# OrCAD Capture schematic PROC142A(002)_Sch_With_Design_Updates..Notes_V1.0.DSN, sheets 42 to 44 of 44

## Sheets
42 42. OSCILLATOR: size C; title: OSCILLATOR
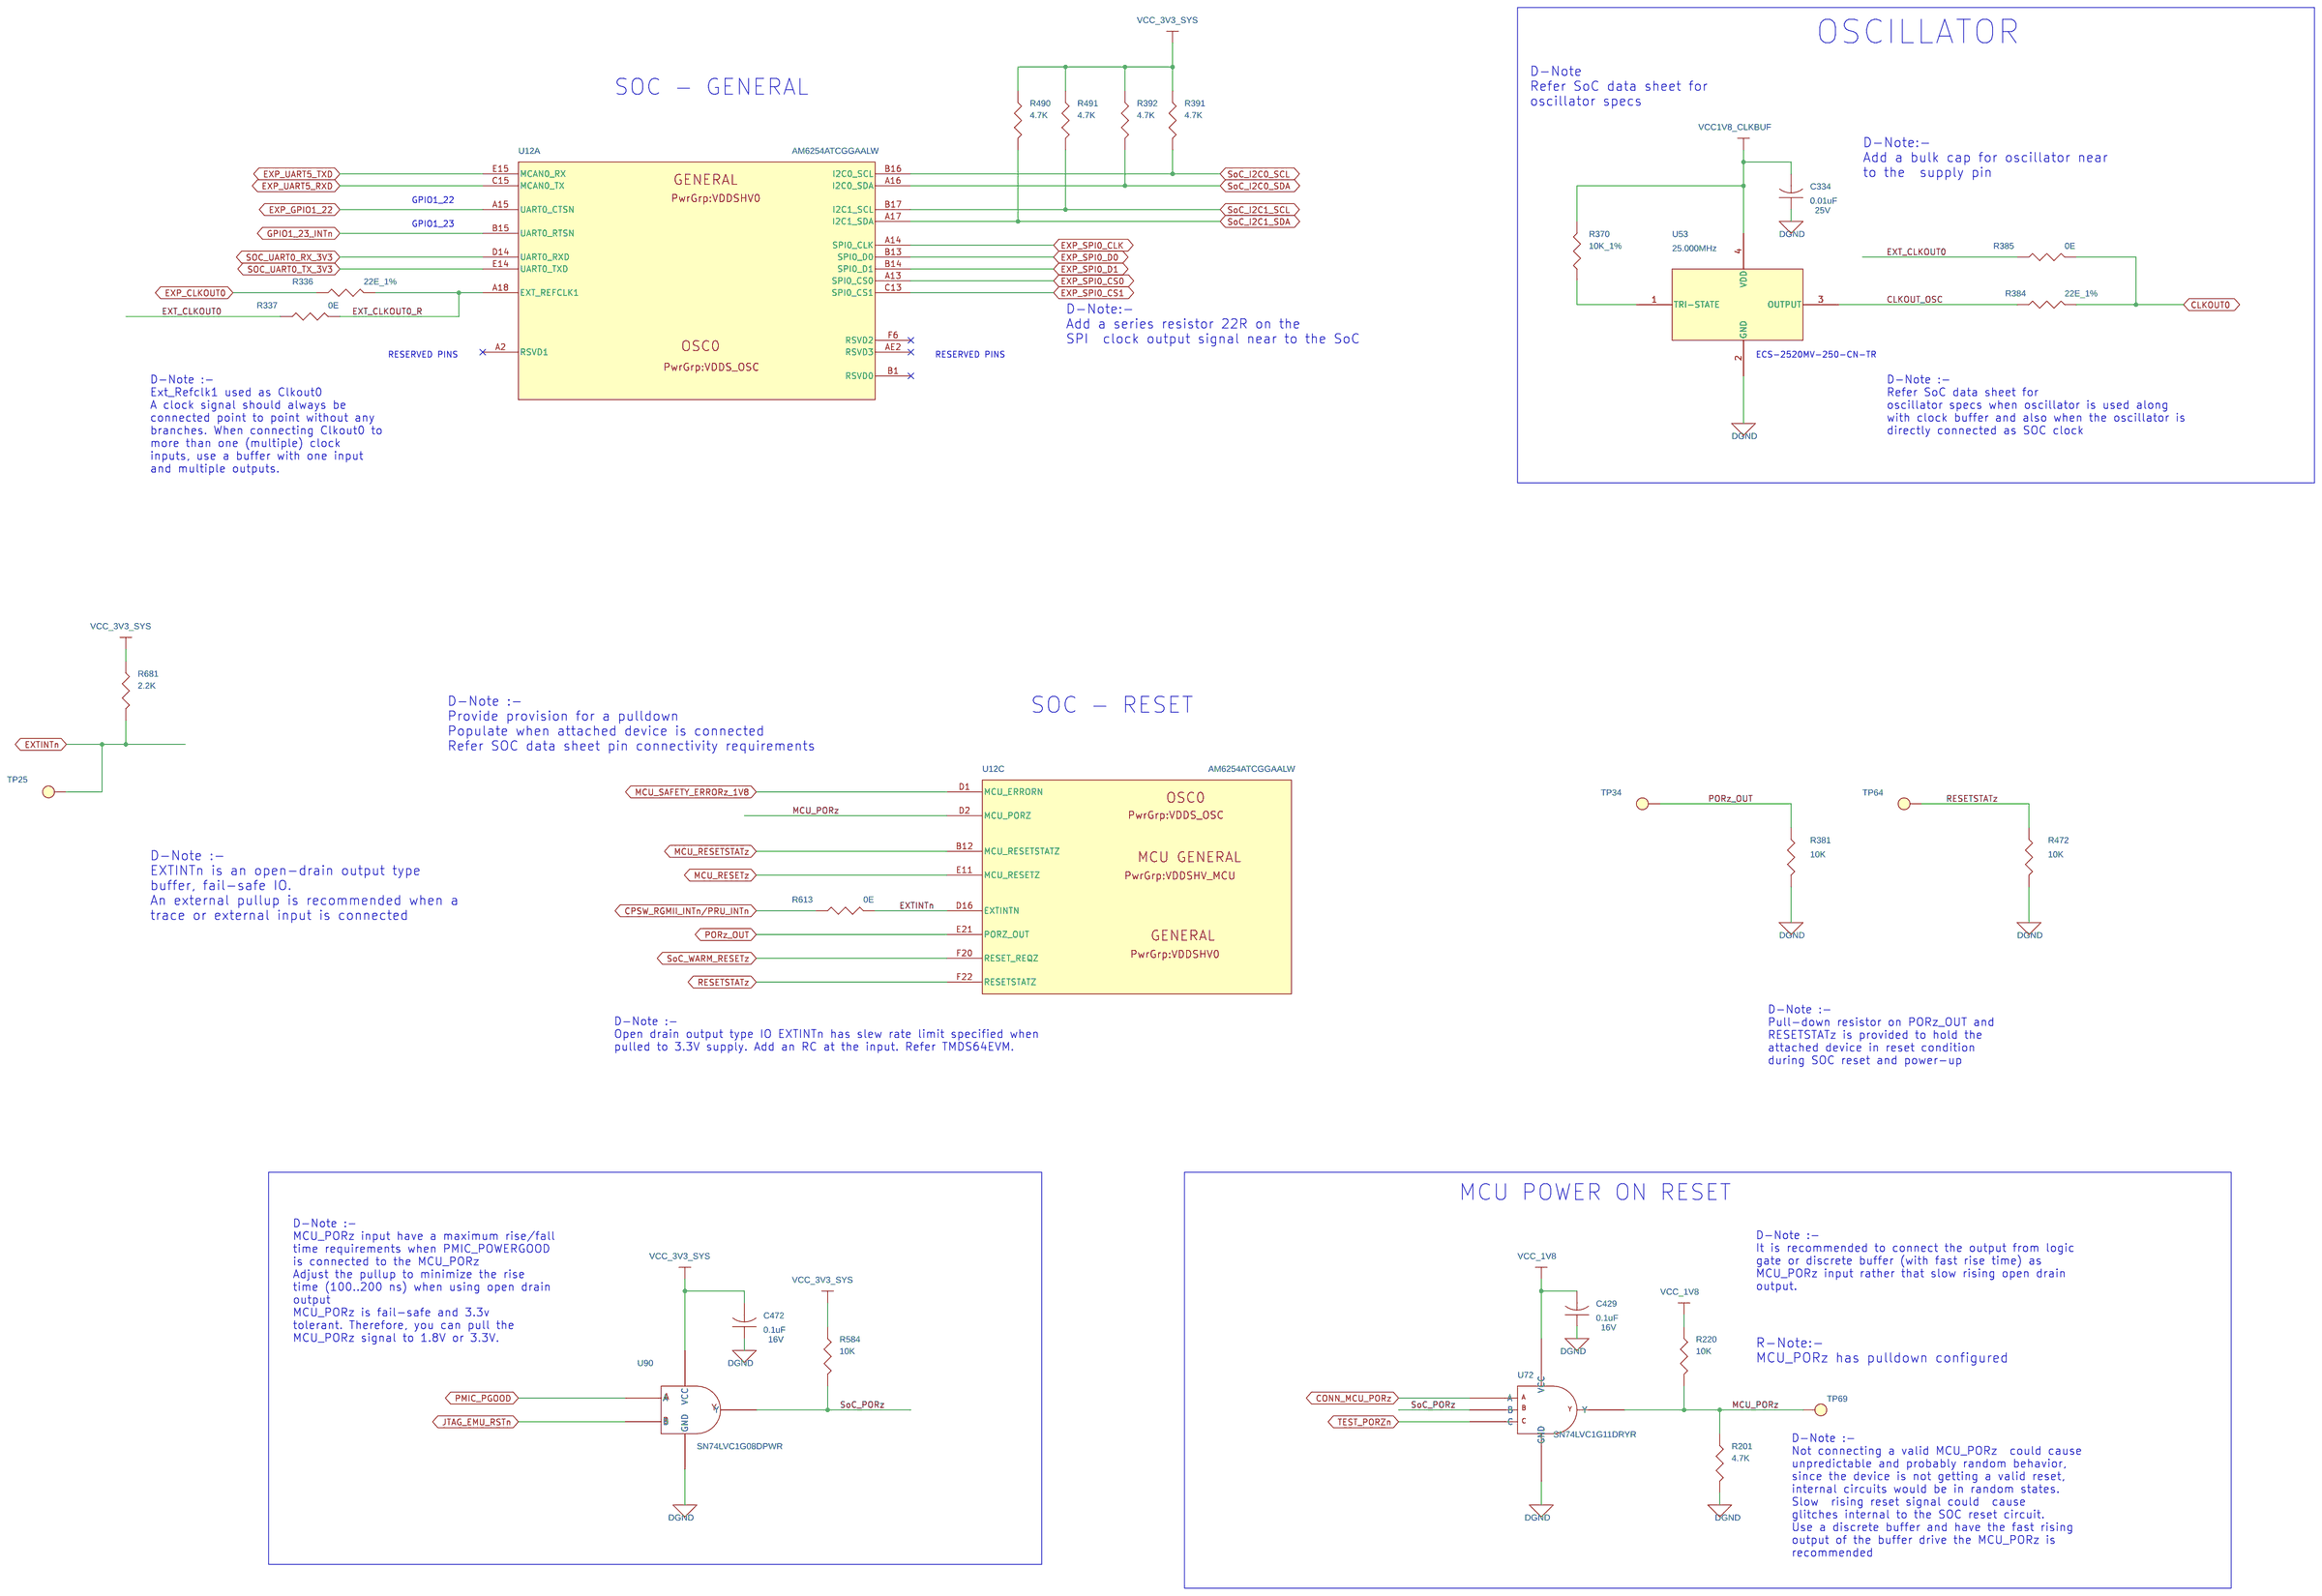
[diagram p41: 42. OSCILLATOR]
43 43. RESET: size C; title: RESET
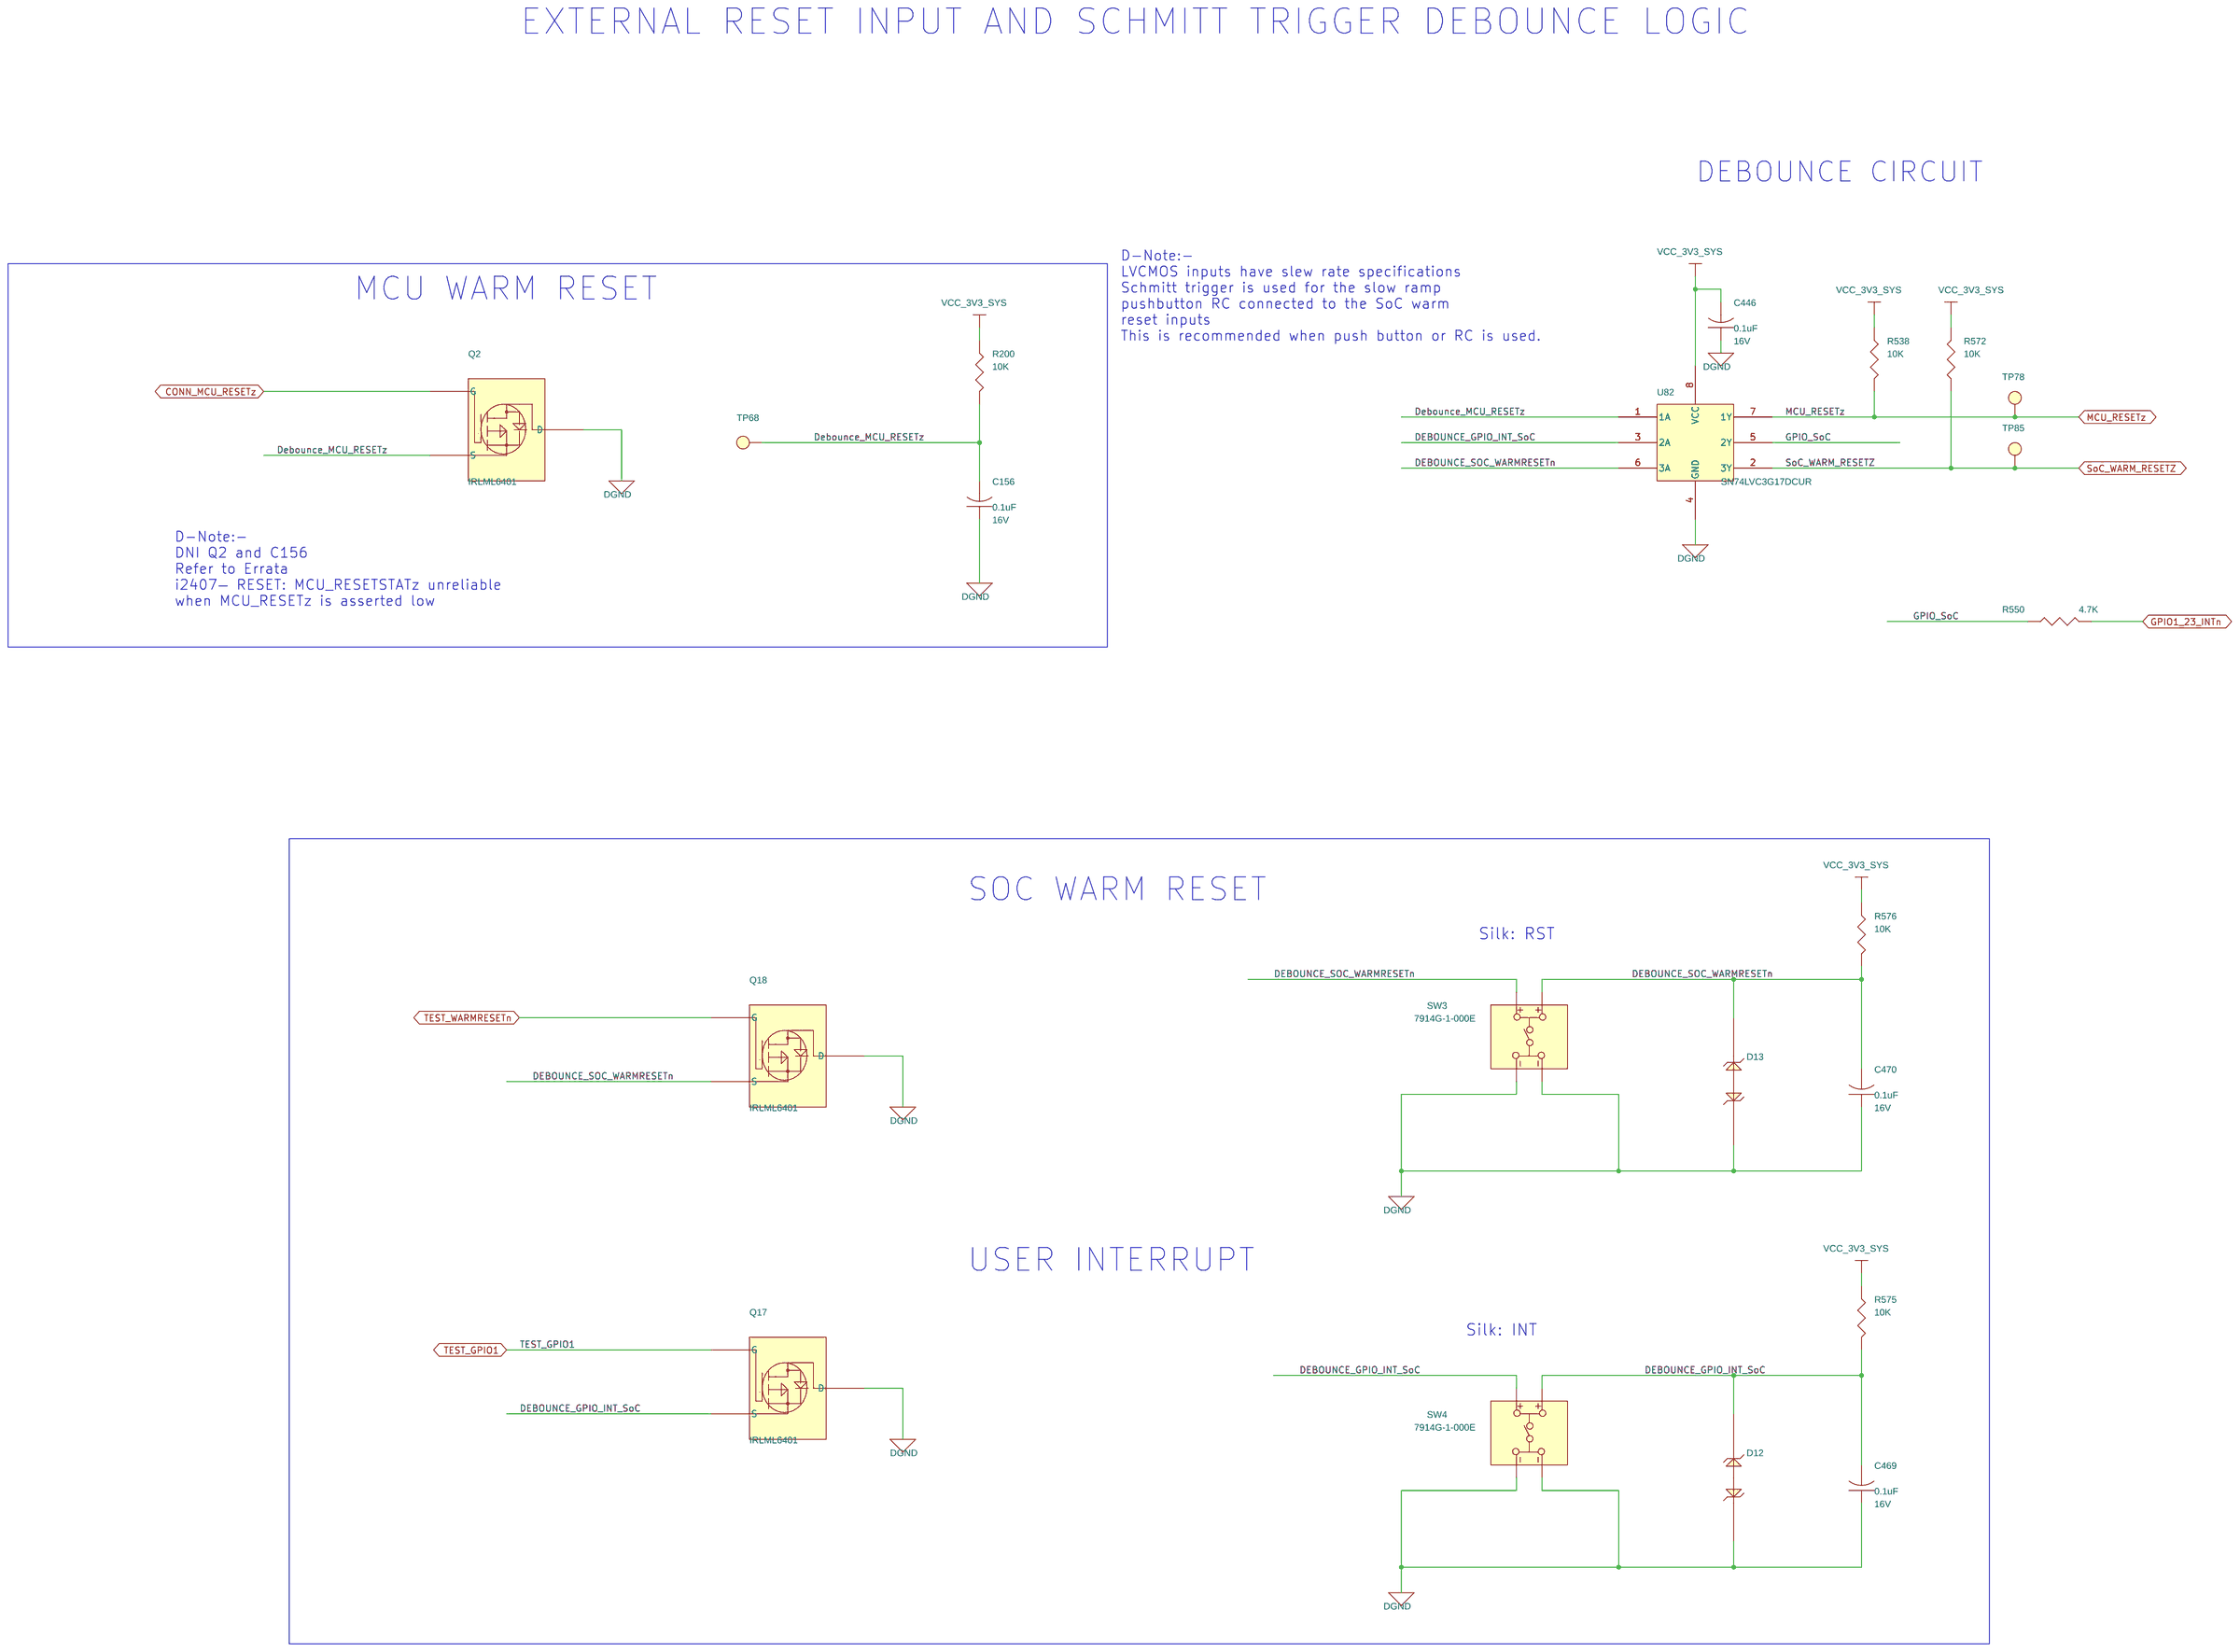
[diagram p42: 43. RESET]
44 44. ACCESSORIES: title: HARDWARE SCHEMATICS
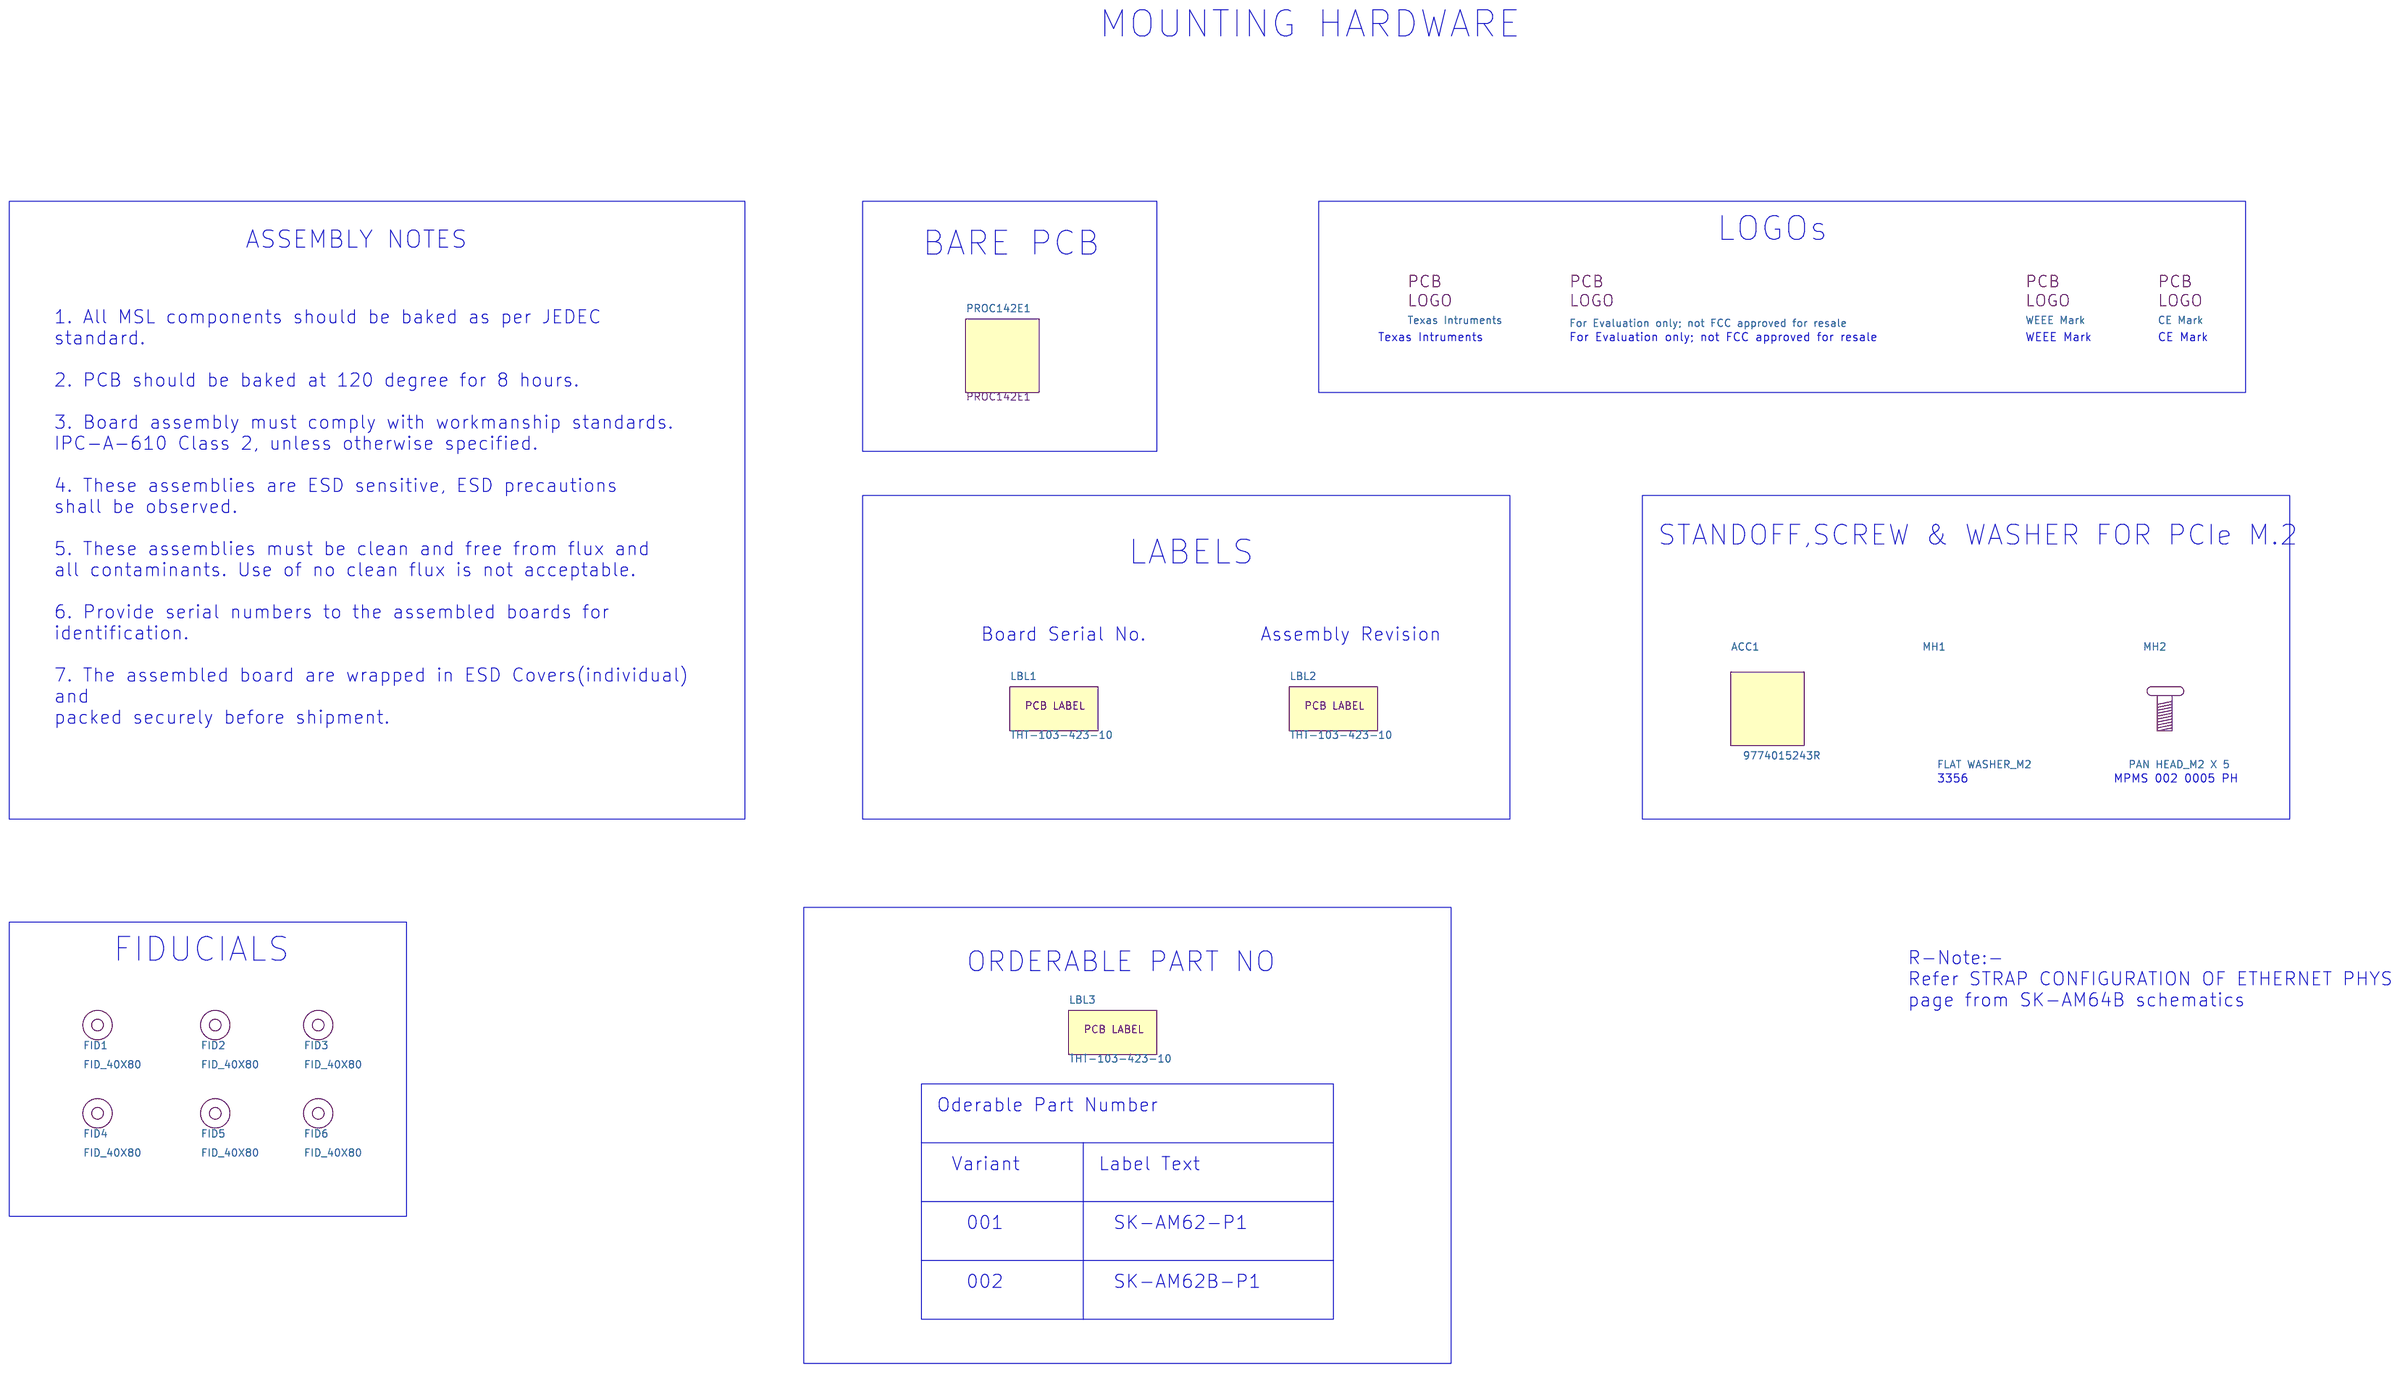
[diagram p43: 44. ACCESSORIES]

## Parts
sheet 42. OSCILLATOR
C334  0.01uF  [CAP0201_0-5]
C429  0.1uF  [CAP0201_0-5]
C472  0.1uF  [CAP0201_0-5]
R201  4.7K  [RES0201_0-5]
R220  10K  [RES0201_0-5]
R336  22E_1%  [RES0201_0-5]
R337  0E  [RES0201_0-5]
R370  10K_1%  [RES0201_0-5]
R381  10K  [RES0201_0-5]
R384  22E_1%  [RES0201_0-5]
R385  0E  [RES0201_0-5]
R391  4.7K  [RES0201_0-5]
R392  4.7K  [RES0201_0-5]
R472  10K  [RES0201_0-5]
R490  4.7K  [RES0201_0-5]
R491  4.7K  [RES0201_0-5]
R584  10K  [RES0201_0-5]
R613  0E  [RES0201_0-5]
R681  2.2K  [RES0201_0-5]
TP25  TP20_SMD  [TP20_SMD]
TP34  TP20_SMD  [TP20_SMD]
TP64  TP20_SMD  [TP20_SMD]
TP69  TP20_SMD  [TP20_SMD]
U12  AM6254ATCGGAALW  [BGA425_19-68_510X510_0-7]  (sections A,B,C,D,E,F,G,H,I,J,K,L,M,N,O,P,Q,R)
U53  25.000MHz  [OSC4_ECS-2520MV_100X80_SMD_0-9]
U72  SN74LVC1G11DRYR  [SON6_SN74LVC2G17_40X60_0-6]
U90  SN74LVC1G08DPWR  [X2SON5_TLV7021_30X30_0-4]
sheet 43. RESET
C156  0.1uF  [CAP0201_0-5]
C446  0.1uF  [CAP0201_0-5]
C469  0.1uF  [CAP0201_0-5]
C470  0.1uF  [CAP0201_0-5]
D12  TPD1E10B06DPYR  [DIO_DFN0402_0-5]
D13  TPD1E10B06DPYR  [DIO_DFN0402_0-5]
Q2  IRLML6401  [TO_SOT23-123]
Q17  IRLML6401  [TO_SOT23-123]
Q18  IRLML6401  [TO_SOT23-123]
R200  10K  [RES0201_0-5]
R538  10K  [RES0201_0-5]
R550  4.7K  [RES0201_0-5]
R572  10K  [RES0201_0-5]
R575  10K  [RES0201_0-5]
R576  10K  [RES0201_0-5]
SW3  7914G-1-000E  [SW4_100X216_200X200_SMD_4-2]
SW4  7914G-1-000E  [SW4_100X216_200X200_SMD_4-2]
TP68  TP20_SMD  [TP20_SMD]
TP78  TP20_SMD  [TP20_SMD]
TP85  TP20_SMD  [TP20_SMD]
U82  SN74LVC3G17DCUR  [VSSOP8_19-68_85X95_0-9]
sheet 44. ACCESSORIES
ACC1  9774015243R  [NA]
FID1  FID_40X80  [FID_40X80]
FID2  FID_40X80  [FID_40X80]
FID3  FID_40X80  [FID_40X80]
FID4  FID_40X80  [FID_40X80]
FID5  FID_40X80  [FID_40X80]
FID6  FID_40X80  [FID_40X80]
LBL1  THT-103-423-10  [NA]
LBL2  THT-103-423-10  [NA]
LBL3  THT-103-423-10  [NA]
LOGO1  Texas Intruments  [TI_Stacked_Overlay_Small]
LOGO2  For Evaluation only; not FCC approved for resale  [FCC_disclaimer]
LOGO3  WEEE Mark  [TI_Stacked_Overlay_Small]
LOGO4  CE Mark  [TI_Stacked_Overlay_Small]
MH1  FLAT WASHER_M2  [NA]
MH2  PAN HEAD_M2 X 5  [NA]
PCB1  PROC142E1

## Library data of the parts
C334 = CAP: CAP CERAMIC 0.01uF 25V 10% X5R 0201; Chkd/date: MANIRAJA/230118; Crtd /date: MANIRAJA/230118; Custom_Duty: 15%; Customs_HS_Code: 85322990; Distributor_name: DIGIKEY; Distributor_part_number: GRM033R61E103KA12J-ND; Footprint Path: Y:\MIS_DATABASE\Library\ALTIUM_TOOL\PCB_FOOTPRINTS\Altium_Footprint_Lib.PcbLib; Height: 0.33MM; Library Path: Y:\MIS_DATABASE\Library\ALTIUM_TOOL\SCHEMATICS_PARTS\MS_DISCRETE_Library.schlib; Mfr_name: MURATA; Mfr_part_number: GRM033R61E103KA12J; Mistral Part No: 120018010007-R; Package: 0201; Part_type: CAPACITORS\CERAMIC; Project: TI_MAXIE_CPB; RoHS: RoHS; Temperature: -55°C+85°C; Tolerance: 10%; Voltage: 25V; Wattage: NA; Weight: 0.33mg; Datasheet: Y:\MIS_DATABASE\DATASHEETS\CAPACITORS\GRM033R61E103KA12.PDF
C156 C429 C446 C469 C470 C472 = CAP: CAP CERAMIC 0.1uF 16V 10% X5R 0201; Alt_Mfr_name: YAGEO AMERICA; Alt_Mfr_part_number: CC0402KRX5R8BB104; Chkd/date: MANIRAJA/230118; Crtd /date: MANIRAJA/230118; Custom_Duty: 15%; Customs_HS_Code: 85322990; Distributor_name: DIGIKEY; Distributor_part_number: 490-14305-1-ND; Footprint Path: Y:\MIS_DATABASE\Library\ALTIUM_TOOL\PCB_FOOTPRINTS\Altium_Footprint_Lib.PcbLib; Height: 0.33MM; Library Path: Y:\MIS_DATABASE\Library\ALTIUM_TOOL\SCHEMATICS_PARTS\MS_DISCRETE_Library.schlib; Mfr_name: MURATA; Mfr_part_number: GRM033R61C104KE14D; Mistral Part No: 120009030072-R; Package: 0201; Part_type: CAPACITORS\CERAMIC; Project: TI_MAXIE_CPB; RoHS: RoHS; Temperature: -55°C+85°C; Tolerance: 10%; Voltage: 16V; Wattage: NA; Weight: 0.33mg; Datasheet: Y:\MIS_DATABASE\DATASHEETS\CAPACITORS\GRM033R61C104KE14.PDF
R201 R391 R392 R490 R491 = RESISTOR: RES 4.7K 1/20W 5% 0201; Chkd/date: MANIRAJA/200921; Crtd /date: ALVY/200921; Custom_Duty: 15%; Customs_HS_Code: 85332119; Distributor_name: DIGIKEY; Distributor_part_number: 311-4.7KNCT-ND; Footprint Path: Y:\MIS_DATABASE\Library\ALTIUM_TOOL\PCB_FOOTPRINTS\Altium_Footprint_Lib.PcbLib; Height: 0.26MM; Library Path: Y:\MIS_DATABASE\Library\ALTIUM_TOOL\SCHEMATICS_PARTS\MS_DISCRETE_Library.schlib; Mfr_name: YAGEO AMERICA; Mfr_part_number: RC0201JR-074K7L; Mistral Part No: 110021090007-R; Package: 0201; Part_type: RESISTORS\FIXED; Project: TI_AM62x SKEVM_BRD; RoHS: RoHS; Temperature: -55°C+125°C; Tolerance: 5%; Voltage: NA; Wattage: 1/20W; Weight: 0.17mg; Datasheet: Y:\MIS_DATABASE\DATASHEETS\RESISTORS\RCXXXXL-SER_MAR18.PDF
R200 R220 R381 R472 R538 R572 R575 R576 R584 = RESISTOR: RES 10K 1/20W 5% 0201; Chkd/date: MANIRAJA/050517; Crtd /date: MANIRAJA/050517; Custom_Duty: 15%; Customs_HS_Code: 85332119; Distributor_name: DIGIKEY; Distributor_part_number: 311-10KNCT-ND; Footprint Path: Y:\MIS_DATABASE\Library\ALTIUM_TOOL\PCB_FOOTPRINTS\Altium_Footprint_Lib.PcbLib; Height: 0.26MM; Library Path: Y:\MIS_DATABASE\Library\ALTIUM_TOOL\SCHEMATICS_PARTS\MS_DISCRETE_Library.schlib; Mfr_name: YAGEO AMERICA; Mfr_part_number: RC0201JR-0710KL; Mistral Part No: 110010070051-R; Package: 0201; Part_type: RESISTORS\FIXED; Project: GOLDEN-I LITE; RoHS: RoHS; Temperature: -55°C+125°C; Tolerance: 5%; Voltage: NA; Wattage: 1/20W; Weight: 0.17mg; Datasheet: Y:\MIS_DATABASE\DATASHEETS\RESISTORS\RCXXXXL-SER_MAR18.PDF
R336 R384 = RESISTOR: RES 22E 1/20W 1% 0201; Chkd/date: MAZHAR/140709; Crtd /date: MAZHAR/220807; Custom_Duty: 15%; Customs_HS_Code: 85332119; Distributor_name: DIGIKEY; Distributor_part_number: P22.0ABCT-ND; Footprint Path: Y:\MIS_DATABASE\Library\ALTIUM_TOOL\PCB_FOOTPRINTS\Altium_Footprint_Lib.PcbLib; Height: 0.26MM; Library Path: Y:\MIS_DATABASE\Library\ALTIUM_TOOL\SCHEMATICS_PARTS\MS_DISCRETE_Library.schlib; Mfr_name: PANASONIC-ECG; Mfr_part_number: ERJ-1GEF22R0C; Mistral Part No: 110009030522-R; Package: 0201; Part_type: RESISTORS\FIXED; Project: V8TS; RoHS: RoHS; Temperature: -55°C+125°C; Tolerance: 1%; Voltage: NA; Wattage: 1/20W; Weight: 0.15mg; Datasheet: Y:\MIS_DATABASE\DATASHEETS\RESISTORS\PAN-ERJSER_NOV17.PDF
R337 R385 R613 = RESISTOR: RES 0E 1/20W 5% 0201; Chkd/date: NAVEED/301214; Crtd /date: MUDDU/120710; Custom_Duty: 15%; Customs_HS_Code: 85332119; Distributor_name: DIGIKEY; Distributor_part_number: 311-0.0NCT-ND; Footprint Path: Y:\MIS_DATABASE\Library\ALTIUM_TOOL\PCB_FOOTPRINTS\Altium_Footprint_Lib.PcbLib; Height: 0.26MM; Library Path: Y:\MIS_DATABASE\Library\ALTIUM_TOOL\SCHEMATICS_PARTS\MS_DISCRETE_Library.schlib; Mfr_name: YAGEO AMERICA; Mfr_part_number: RC0201JR-070RL; Mistral Part No: 110010070067-R; Package: 0201; Part_type: RESISTORS\FIXED; Project: PB_BUGBASE; RoHS: RoHS; Temperature: -55°C+125°C; Tolerance: 5%; Voltage: NA; Wattage: 1/20W; Weight: 0.17mg; Datasheet: Y:\MIS_DATABASE\DATASHEETS\RESISTORS\RCXXXXL-SER_MAR18.PDF
R370 = RESISTOR: RES 10K 1/20W 1% 0201; Chkd/date: VASANTHA/270117; Crtd /date: MANIRAJA/270117; Custom_Duty: 15%; Customs_HS_Code: 85332119; Distributor_name: DIGIKEY; Distributor_part_number: 311-10.0KMCT-ND; Footprint Path: Y:\MIS_DATABASE\Library\ALTIUM_TOOL\PCB_FOOTPRINTS\Altium_Footprint_Lib.PcbLib; Height: 0.26MM; Library Path: Y:\MIS_DATABASE\Library\ALTIUM_TOOL\SCHEMATICS_PARTS\MS_DISCRETE_Library.schlib; Mfr_name: YAGEO AMERICA; Mfr_part_number: RC0201FR-0710KL; Mistral Part No: 110011040018-R; Package: 0201; Part_type: RESISTORS\FIXED; Project: GOLDEN-I LITE; RoHS: RoHS; Temperature: -55°C+125°C; Tolerance: 1%; Voltage: NA; Wattage: 1/20W; Weight: 0.17mg; Datasheet: Y:\MIS_DATABASE\DATASHEETS\RESISTORS\RCXXXXL-SER_MAR18.PDF
R681 = RESISTOR: RES 2.2K 1/20W 5% 0201; Chkd/date: VASANTHA/010117; Crtd /date: MAZHAR/010605; Custom_Duty: 15%; Customs_HS_Code: 85332119; Distributor_name: DIGIKEY; Distributor_part_number: P2.2KAGCT-ND; Footprint Path: Y:\MIS_DATABASE\Library\ALTIUM_TOOL\PCB_FOOTPRINTS\Altium_Footprint_Lib.PcbLib; Height: 0.26MM; Library Path: Y:\MIS_DATABASE\Library\ALTIUM_TOOL\SCHEMATICS_PARTS\MS_DISCRETE_Library.schlib; Mfr_name: PANASONIC-ECG; Mfr_part_number: ERJ-1GEJ222C; Mistral Part No: 110009030427-R; Package: 0201; Part_type: RESISTORS\FIXED; Project: G4SLIM; RoHS: RoHS; Temperature: -55°C+125°C; Tolerance: 5%; Voltage: NA; Wattage: 1/20W; Weight: 0.15mg; Datasheet: Y:\MIS_DATABASE\DATASHEETS\RESISTORS\PAN-ERJXGE-FEB06.PDF
TP25 TP34 TP64 TP68 TP69 TP78 TP85 = TESTPOINT: TESTPOINT CIR 20 SMD; Chkd/date: SHREESHAIL/171006; Crtd /date: MAZHAR/171006; Custom_Duty: NA; Customs_HS_Code: NA; Distributor_name: NA; Distributor_part_number: NA; Footprint Path: Y:\MIS_DATABASE\Library\ALTIUM_TOOL\PCB_FOOTPRINTS\Altium_Footprint_Lib.PcbLib; Height: NA; Library Path: Y:\MIS_DATABASE\Library\ALTIUM_TOOL\SCHEMATICS_PARTS\MS_DISCRETE_Library.schlib; MECHANICAL 3D STEP FILE: NA; Mfr_name: LOCAL; Mistral Part No: NA; Package: SMD; Project: BT MODULE_CSRBC04; RoHS: NA; Temperature: NA; Tolerance: NA; Voltage: NA; Wattage: NA; Weight: NA; Datasheet: NA
U12 = AM62-EVM_BGA425: IC AM62 SoC MICROPROCESSOR BGA425; Chkd/date: ALVY/110621; Crtd /date: MANIRAJA/110621; Custom_Duty: 15%; Customs_HS_Code: 85423100; Distributor_name: NA; Distributor_part_number: NA; Footprint Path: Y:\MIS_DATABASE\Library\ALTIUM_TOOL\PCB_FOOTPRINTS\Altium_Footprint_Lib.PcbLib; Height: 0.65MM; Library Path: Y:\MIS_DATABASE\Library\ALTIUM_TOOL\SCHEMATICS_PARTS\MS_MICROPROCESSOR_Library.schlib; Mfr_name: TEXAS INSTRUMENTS; Mistral Part No: 141221060001; Package: BGA425; Part_type: ICS\DIGITAL\MICROPROCESSOR; Project: AM62_EVM_BRD; RoHS: NA; Temperature: NA; Tolerance: NA; Voltage: NA; Wattage: NA; Weight: NA; Datasheet: Y:\MIS_DATABASE\DATASHEETS\ICS\DIGITAL\MICROCONTROLLER\AM62-SoC_SVB.PDF
U53 = OSC4_ASFL3: OSC 25.000MHz CMOS SMD; Chkd/date: MANIRAJA/181120; Crtd /date: ALVY/181120; Custom_Duty: 24%; Customs_HS_Code: 85437099; Distributor_name: DIGIKEY; Distributor_part_number: XC2752CT-ND; Footprint Path: Y:\MIS_DATABASE\Library\ALTIUM_TOOL\PCB_FOOTPRINTS\Altium_Footprint_Lib.PcbLib; Height: 0.90MM; Library Path: Y:\MIS_DATABASE\Library\ALTIUM_TOOL\SCHEMATICS_PARTS\MS_DISCRETE_Library.schlib; Mfr_name: ECS INC; Mfr_part_number: ECS-2520MV-250-CN-TR; Mistral Part No: 130020110041-R; Package: SMD; Part_type: OSCILLATORS; Project: AM64X_SKEVM; RoHS: RoHS; Temperature: -40°C+85°C; Tolerance: NA; Voltage: NA; Wattage: NA; Weight: 311mg; Datasheet: Y:\MIS_DATABASE\DATASHEETS\MISC\CRY_OSC\ECS-2520MV.PDF
U72 = SN74LVC1G11DCKR_SC70-6: IC SINGLE 3-INPUT POSITIVE-AND GATE SON6; Chkd/date: MANIRAJA/270121; Crtd /date: ALVY/270121; Custom_Duty: 15%; Customs_HS_Code: 85423100; Distributor_name: DIGIKEY; Distributor_part_number: 296-30120-1-ND; Footprint Path: Y:\MIS_DATABASE\Library\ALTIUM_TOOL\PCB_FOOTPRINTS\Altium_Footprint_Lib.PcbLib; Height: 0.60MM; Library Path: Y:\MIS_DATABASE\Library\ALTIUM_TOOL\SCHEMATICS_PARTS\MS_GATE_Library.schlib; Mfr_name: TEXAS INSTRUMENTS; Mistral Part No: 141021010013-R; Package: SON6; Part_type: ICS\DIGITAL\GATES; Project: AM64X_SKEVM; RoHS: RoHS; Temperature: -40°C+125°C; Tolerance: NA; Voltage: NA; Wattage: NA; Weight: 33mg; Datasheet: Y:\MIS_DATABASE\DATASHEETS\ICS\DIGITAL\GATES\SN74LVC1G_NOV16.PDF
U90 = 74AHC1G08GW_SOT353-5: IC SINGLE 2-INPUT POSITIVE-AND GATE X2SON5; Chkd/date: MANIRAJA/141020; Crtd /date: ALVY/131020; Custom_Duty: 15%; Customs_HS_Code: 85423100; Distributor_name: DIGIKEY; Distributor_part_number: 296-40549-1-ND; Footprint Path: Y:\MIS_DATABASE\Library\ALTIUM_TOOL\PCB_FOOTPRINTS\Altium_Footprint_Lib.PcbLib; Height: 0.40MM; Library Path: Y:\MIS_DATABASE\Library\ALTIUM_TOOL\SCHEMATICS_PARTS\MS_GATE_Library.schlib; Manufacturer: TEXAS INSTRUMENTS; Mistral Part No: 141020100009-R; Package: X2SON5; Part_type: ICS\DIGITAL\GATES; Project: AM64X_SKEVM; RoHS: RoHS; Temperature: -40°C+125°C; Tolerance: NA; Voltage: NA; Wattage: NA; Weight: 0.6mg; Datasheet: Y:\MIS_DATABASE\DATASHEETS\ICS\DIGITAL\GATES\SN74LVC1G08XX.PDF
D12 D13 = DIODE_SOD323: DIODE 1CH ESD PROTECTION X1SON2; Chkd/date: MANIRAJA/040420; Crtd /date: VASANTHA/181114; Custom_Duty: 15%; Customs_HS_Code: 85423100; Distributor_name: DIGIKEY; Distributor_part_number: 296-30406-1-ND; Footprint Path: Y:\MIS_DATABASE\Library\ALTIUM_TOOL\PCB_FOOTPRINTS\Altium_Footprint_Lib.PcbLib; Height: 0.45MM; Library Path: Y:\MIS_DATABASE\Library\ALTIUM_TOOL\SCHEMATICS_PARTS\MS_DISCRETE_Library.schlib; Mfr_name: TEXAS INSTRUMENTS; Mistral Part No: 130014110022-R; Package: X1SON2; Part_type: DIODE; Project: GALILEO_EVM; RoHS: RoHS; Temperature: -40°C+125°C; Tolerance: NA; Voltage: NA; Wattage: NA; Weight: 1mg; Datasheet: Y:\MIS_DATABASE\DATASHEETS\ICS\INTERFACE\TPD1E10B06-SER.PDF
Q2 Q17 Q18 = MOSFET_IRLML6401TR: TRANSISTOR MOSFET P-CHANNEL SOT23-3; Chkd/date: SHREESHAIL/020206; Crtd /date: MAZHAR/040505; Custom_Duty: 15%; Customs_HS_Code: 85412900; Distributor_name: DIGIKEY; Distributor_part_number: IRLML6401PBFCT-ND; Height: 1.11MM; Mfr_name: IRF; Mfr_part_number: IRLML6401TRPBF; Mistral Part No: 130009031213-P; Package: SOT23-3; Part_type: TRANSISTOR\MOSFET; Project: G4_SVGA; RoHS: Pb-Free; Temperature: -55°C+150°C; Tolerance: NA; Voltage: NA; Wattage: NA; Weight: NA; Datasheet: Y:\MIS_DATABASE\DATASHEETS\DISCRETES\TRANSISTORS_FETS\IRLML6401.PDF
R550 = RESISTOR: RES 4.7K 1/20W 5% 0201; Chkd/date: MANIRAJA/200921; Crtd /date: ALVY/200921; Custom_Duty: 15%; Customs_HS_Code: 85332119; Distributor_name: DIGIKEY; Distributor_part_number: 311-4.7KNCT-ND; Footprint Path: Y:\MIS_DATABASE\Library\ALTIUM_TOOL\PCB_FOOTPRINTS\Altium_Footprint_Lib.PcbLib; Height: 0.26MM; Library Path: Y:\MIS_DATABASE\Library\ALTIUM_TOOL\SCHEMATICS_PARTS\MS_DISCRETE_Library.schlib; Manufacturer: YAGEO AMERICA; Mfr_name: YAGEO AMERICA; Mfr_part_number: RC0201JR-074K7L; Mistral Part No: 110021090007-R; Package: 0201; Part_type: RESISTORS\FIXED; Project: TI_AM62x SKEVM_BRD; RoHS: RoHS; Temperature: -55°C+125°C; Tolerance: 5%; Voltage: NA; Wattage: 1/20W; Weight: 0.17mg; Datasheet: Y:\MIS_DATABASE\DATASHEETS\RESISTORS\RCXXXXL-SER_MAR18.PDF
SW3 SW4 = 7914G-1-000E__7914G: SWITCH SPST-NO 4MM SQ SMD 7914G; Chkd/date: VASANTHA/271216; Crtd /date: BAVISH/051010; Custom_Duty: 24%; Customs_HS_Code: 85369090; Distributor_name: DIGIKEY; Distributor_part_number: 7914G-000ECT-ND; Height: 4.19MM; Library Ref: 7914G-1-000E _7914G; Mfr_name: BOURNS; Mistral Part No: 130015110004-R; Package: 7914G; Part_type: ELECTRO-MECHANICAL\SWITCH; Project: AAAUC; RoHS: RoHS; Temperature: -55°C+125°C; Tolerance: NA; Voltage: NA; Wattage: NA; Weight: NA; Datasheet: Y:\MIS_DATABASE\DATASHEETS\ICS\DIGITAL\COMBINATIONAL\7914G-1-000E.PDF
U82 = SN74LVC3G17DCUR_VSSOP8: IC TRIPLE SCHMITT-TRIGGER BUFFER VSSOP8; Chkd/date: MANIRAJA/280917; Crtd /date: MANIRAJA/280917; Custom_Duty: 15%; Customs_HS_Code: 85423100; Distributor_name: DIGIKEY; Distributor_part_number: 296-18818-1-ND; Height: 0.90MM; Mfr_name: TEXAS INSTRUMENTS; Mistral Part No: 141017090019-R; Package: VSSOP8; Part_type: ICS\DIGITAL\COMBINATIONAL; Project: TI_MAXIE_CPB; RoHS: RoHS; Temperature: -40°C+125°C; Tolerance: NA; Voltage: NA; Wattage: NA; Weight: 9.6mg; Datasheet: Y:\MIS_DATABASE\DATASHEETS\ICS\DIGITAL\COMBINATIONAL\SN74LVC3G17.PDF
ACC1 = ACCESSORY: STANDOFF BOARD TO BOARD 1.50MM LENGTH FEMALE M2 THREADED SS; Chkd/date: MANIRAJA/280219; Crtd /date: ALVY/280219; Distributor_name: DIGIKEY; Distributor_part_number: 732-7069-1-ND; Mfr_name: WURTH ELECTRONICS; Mistral Part No: 160019020049-R; Package: SS; Part_type: MECHANICAL\STANDOFF; Project: TI_J7ES_EVM_CP; RoHS: RoHS; Weight: 178mg; Datasheet: Y:\MIS_DATABASE\DATASHEETS\MISC\MECHANICAL\9774015243R.PDF
FID1-FID6 = Fiducial
LBL1-LBL3 = ACCESSORY_THT-3-423-10: ACCESSORIE 1 WORKHORSE POLYSTER LABLE 0.25" X 1"; Chkd/date: MANIRAJA/270218; Crtd /date: ALVY/260218; Footprint Path: Y:\MIS_DATABASE\Library\ALTIUM_TOOL\PCB_FOOTPRINTS\Altium_Footprint_Lib.PcbLib; Library Path: Y:\MIS_DATABASE\Library\ALTIUM_TOOL\SCHEMATICS_PARTS\MS_MECHANICAL_Library.schlib; Mfr_name: BRADY; Mistral Part No: 160018020185; Part_type: ACCESSORIES; Project: TI_MAXIE_CPB
LOGO1 LOGO3 LOGO4 = TI_Logo
LOGO2 = FCC_disclaimer
MH1 = WASHER_FLAT: FLAT WASHER FOR M2 NYLON; Chkd/date: MANIRAJA/110319; Crtd /date: ALVY/110319; Distributor_name: DIGIKEY; Distributor_part_number: 36-3356-ND; Mfr_name: KEYSTONE; Mfr_part_number: 3356; Mistral Part No: 160019030017-R; Package: NYLON; Part_type: MECHANICAL\WASHERS; Project: TI_J7ES_EVM_CP; RoHS: RoHS; Datasheet: Y:\MIS_DATABASE\DATASHEETS\MISC\MECHANICAL\3356.PDF
MH2 = SCREW_PAN: PHILLIPS PAN HEAD SCREW - M2 X 5; Chkd/date: MANIRAJA/150319; Crtd /date: MANIRAJA/150319; Distributor_name: DIGIKEY; Distributor_part_number: H738-ND; Height: 5.00MM; Mfr_name: B AND F FASTENER; Mfr_part_number: MPMS 002 0005 PH; Mistral Part No: 160019030026-R; Part_type: MECHANICAL\SCREWS; Project: TI_J7ES_EVM_CP; RoHS: RoHS; Datasheet: Y:\MIS_DATABASE\DATASHEETS\MISC\MECHANICAL\SCREW_MPMSXXX.PDF
PCB1 = PCB: AM62x SKEVM Bare PCB

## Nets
DGND: C156.1 C334.1 C429.1 C446.1 C469.1 C470.1 C472.1 D12.1 D13.1 Q2.3(D) Q17.3(D) Q18.3(D) R201.2 R381.2 R472.2 SW3.1 SW3.4 SW4.1 SW4.4 U53.2(GND) U72.2(GND) U82.4(GND) U90.3(GND) ; also on sheet 1 10 11 12 13 14 15 16 17 18 19 20 21 22 23 24 25 26 27 28 29 30 31 32 33 34 35 36 37 38 39 40 41
VCC1V8_CLKBUF: C334.2 R370.2 U53.4(VDD) ; also on sheet 25
VCC_1V8: C429.2 R220.1 U72.5(VCC) ; also on sheet 12 13 14 18 19 21 25 34 37 39 40
VCC_3V3_SYS: C446.2 C472.2 R200.1 R391.1 R392.1 R490.1 R491.1 R538.1 R572.2 R575.1 R576.1 R584.1 R681.1 U82.8(VCC) U90.5(VCC) ; also on sheet 10 12 13 14 18 19 20 22 23 24 25 26 27 29 30 31 32 33 34 35 36 37 38 39 40 41
CLKOUT0: R384.2 R385.2 ; also on sheet 25
CLKOUT_OSC: R384.1 U53.3(OUTPUT)
CONN_MCU_PORz: U72.1(A) ; also on sheet 34
CONN_MCU_RESETz: Q2.1(G) ; also on sheet 34
CPSW_RGMII_INTn/PRU_INTn: R613.1 ; also on sheet 23 32
DEBOUNCE_GPIO_INT_SoC: C469.2 D12.2 Q17.2(S) R575.2 SW4.2 SW4.3 U82.3(2A)
Debounce_MCU_RESETz: C156.2 Q2.2(S) R200.2 TP68.1(TP) U82.1(1A)
DEBOUNCE_SOC_WARMRESETn: C470.2 D13.2 Q18.2(S) R576.2 SW3.2 SW3.3 U82.6(3A)
EXP_CLKOUT0: R336.1 ; also on sheet 33
EXP_GPIO1_22: U12.A15(UART0_CTSN) ; also on sheet 33
EXP_SPI0_CLK: U12.A14(SPI0_CLK) ; also on sheet 33
EXP_SPI0_CS0: U12.A13(SPI0_CS0) ; also on sheet 33
EXP_SPI0_CS1: U12.C13(SPI0_CS1) ; also on sheet 33
EXP_SPI0_D0: U12.B13(SPI0_D0) ; also on sheet 33
EXP_SPI0_D1: U12.B14(SPI0_D1) ; also on sheet 33
EXP_UART5_RXD: U12.C15(MCAN0_TX) ; also on sheet 33
EXP_UART5_TXD: U12.E15(MCAN0_RX) ; also on sheet 33
EXT_CLKOUT0: R337.1 R385.1
EXT_CLKOUT0_R: R336.2 R337.2 U12.A18(EXT_REFCLK1)
EXTINTn: R613.2 R681.2 TP25.1(TP) U12.D16(EXTINTN) ; also on sheet 13
GPIO1_23_INTn: R550.2 U12.B15(UART0_RTSN) ; also on sheet 39
GPIO_SoC: R550.1 U82.5(2Y)
JTAG_EMU_RSTn: U90.1(B) ; also on sheet 30
MCU_PORz: R201.1 R220.2 TP69.1(TP) U12.D2(MCU_PORZ) U72.4(Y)
MCU_RESETSTATz: U12.B12(MCU_RESETSTATZ) ; also on sheet 32 34
MCU_RESETz: R538.2 TP78.1(TP) U12.E11(MCU_RESETZ) U82.7(1Y)
MCU_SAFETY_ERRORz_1V8: U12.D1(MCU_ERRORN) ; also on sheet 34
PMIC_PGOOD: U90.2(A) ; also on sheet 13 35
PORz_OUT: R381.1 TP34.1(TP) U12.E21(PORZ_OUT) ; also on sheet 20 23 24 27
RESETSTATz: R472.1 TP64.1(TP) U12.F22(RESETSTATZ) ; also on sheet 13 19 20 21 23 24 27 32 33 37 39 40 41
SoC_I2C0_SCL: R391.2 U12.B16(I2C0_SCL) ; also on sheet 10 13 22 32 33 37
SoC_I2C0_SDA: R392.2 U12.A16(I2C0_SDA) ; also on sheet 10 13 22 32 33 37
SOC_I2C1_SCL: R491.2 U12.B17(I2C1_SCL) ; also on sheet 14 22 26 39 40 41
SOC_I2C1_SDA: R490.2 U12.A17(I2C1_SDA) ; also on sheet 14 22 26 39 40 41
SoC_PORz: R584.2 U72.3(B) U90.4(Y)
SOC_UART0_RX_3V3: U12.D14(UART0_RXD) ; also on sheet 31
SOC_UART0_TX_3V3: U12.E14(UART0_TXD) ; also on sheet 31
SoC_WARM_RESETZ: R572.1 TP85.1(TP) U12.F20(RESET_REQZ) U82.2(3Y)
TEST_GPIO1: Q17.1(G) ; also on sheet 1 26
TEST_PORZn: U72.6(C) ; also on sheet 1 26
TEST_WARMRESETn: Q18.1(G) ; also on sheet 1 26
N16947096: R370.1 U53.1(TRI-STATE)

Not connected (* = marked no-connect by the designer): U12 A2(RSVD1)* AE2(RSVD3)* B1(RSVD0)* F6(RSVD2)*

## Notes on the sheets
sheet 42
- OSCILLATOR
- D-Note
  Refer SoC data sheet for
  oscillator specs
- SOC - GENERAL
- D-Note:-
  Add a bulk cap for oscillator near
  to the  supply pin
- GPIO1_22
- GPIO1_23
- D-Note:-
  Add a series resistor 22R on the
  SPI  clock output signal near to the SoC
- RESERVED PINS
- RESERVED PINS
- ECS-2520MV-250-CN-TR
- D-Note :-
  Ext_Refclk1 used as Clkout0
  A clock signal should always be
  connected point to point without any
  branches. When connecting Clkout0 to
  more than one (multiple) clock
  inputs, use a buffer with one input
  and multiple outputs.
- D-Note :-
  Refer SoC data sheet for
  oscillator specs when oscillator is used along
  with clock buffer and also when the oscillator is
  directly connected as SOC clock
- D-Note :-
  Provide provision for a pulldown
  Populate when attached device is connected
  Refer SOC data sheet pin connectivity requirements
- SOC - RESET
- D-Note :-
  EXTINTn is an open-drain output type
  buffer, fail-safe IO.
  An external pullup is recommended when a
  trace or external input is connected
- D-Note :-
  Pull-down resistor on PORz_OUT and
  RESETSTATz is provided to hold the
  attached device in reset condition
  during SOC reset and power-up
- D-Note :-
  Open drain output type IO EXTINTn has slew rate limit specified when
  pulled to 3.3V supply. Add an RC at the input. Refer TMDS64EVM.
- MCU POWER ON RESET
- D-Note :-
  MCU_PORz input have a maximum rise/fall
  time requirements when PMIC_POWERGOOD
  is connected to the MCU_PORz
  Adjust the pullup to minimize the rise
  time (100..200 ns) when using open drain
  output
  MCU_PORz is fail-safe and 3.3v
  tolerant. Therefore, you can pull the
  MCU_PORz signal to 1.8V or 3.3V.
- D-Note :-
  It is recommended to connect the output from logic
  gate or discrete buffer (with fast rise time) as
  MCU_PORz input rather that slow rising open drain
  output.
- R-Note:-
  MCU_PORz has pulldown configured
- D-Note :-
  Not connecting a valid MCU_PORz  could cause
  unpredictable and probably random behavior,
  since the device is not getting a valid reset,
  internal circuits would be in random states.
  Slow  rising reset signal could  cause
  glitches internal to the SOC reset circuit.
  Use a discrete buffer and have the fast rising
  output of the buffer drive the MCU_PORz is
  recommended
sheet 43
- EXTERNAL RESET INPUT AND SCHMITT TRIGGER DEBOUNCE LOGIC
- DEBOUNCE CIRCUIT
- D-Note:-
  LVCMOS inputs have slew rate specifications
  Schmitt trigger is used for the slow ramp
  pushbutton RC connected to the SoC warm
  reset inputs
  This is recommended when push button or RC is used.
- MCU WARM RESET
- D-Note:-
  DNI Q2 and C156
  Refer to Errata
  i2407— RESET: MCU_RESETSTATz unreliable
  when MCU_RESETz is asserted low
- SOC WARM RESET
- Silk: RST
- USER INTERRUPT
- Silk: INT
sheet 44
- MOUNTING HARDWARE
- LOGOs
- ASSEMBLY NOTES
- BARE PCB
- 1. All MSL components should be baked as per JEDEC
  standard.
  2. PCB should be baked at 120 degree for 8 hours.
  3. Board assembly must comply with workmanship standards.
  IPC-A-610 Class 2, unless otherwise specified.
  4. These assemblies are ESD sensitive, ESD precautions
  shall be observed.
  5. These assemblies must be clean and free from flux and
  all contaminants. Use of no clean flux is not acceptable.
  6. Provide serial numbers to the assembled boards for
  identification.
  7. The assembled board are wrapped in ESD Covers(individual)
  and
  packed securely before shipment.
- Texas Intruments
- For Evaluation only; not FCC approved for resale
- WEEE Mark
- CE Mark
- STANDOFF,SCREW & WASHER FOR PCIe M.2
- LABELS
- Board Serial No.
- Assembly Revision
- 3356
- MPMS 002 0005 PH
- FIDUCIALS
- ORDERABLE PART NO
- R-Note:-
  Refer STRAP CONFIGURATION OF ETHERNET PHYS
  page from SK-AM64B schematics
- Oderable Part Number
- Variant
- Label Text
- 001
- SK-AM62-P1
- 002
- SK-AM62B-P1
